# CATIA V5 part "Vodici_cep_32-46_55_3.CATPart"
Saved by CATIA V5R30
Part number: Vodici_cep_32-46_55_3
Definition: E 1000_30-46_55
Nomenclature: E 1000_30-46_55
Source: Unknown
Description: PART--DESC
Bounding box of the stored display mesh (mm): x 163.7 to 210.3, y -160.3 to -113.7, z -101 to 9
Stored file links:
  E:\Bakalarka\Model\Forma_v7\Vodici_cep_32-46_55_3.CATPart
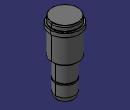
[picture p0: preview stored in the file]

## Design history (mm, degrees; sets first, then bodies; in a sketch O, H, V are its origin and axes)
Body1 "MANIFOLD_SOLID_BREP #3970" (main body)
  Solid1: solid without history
